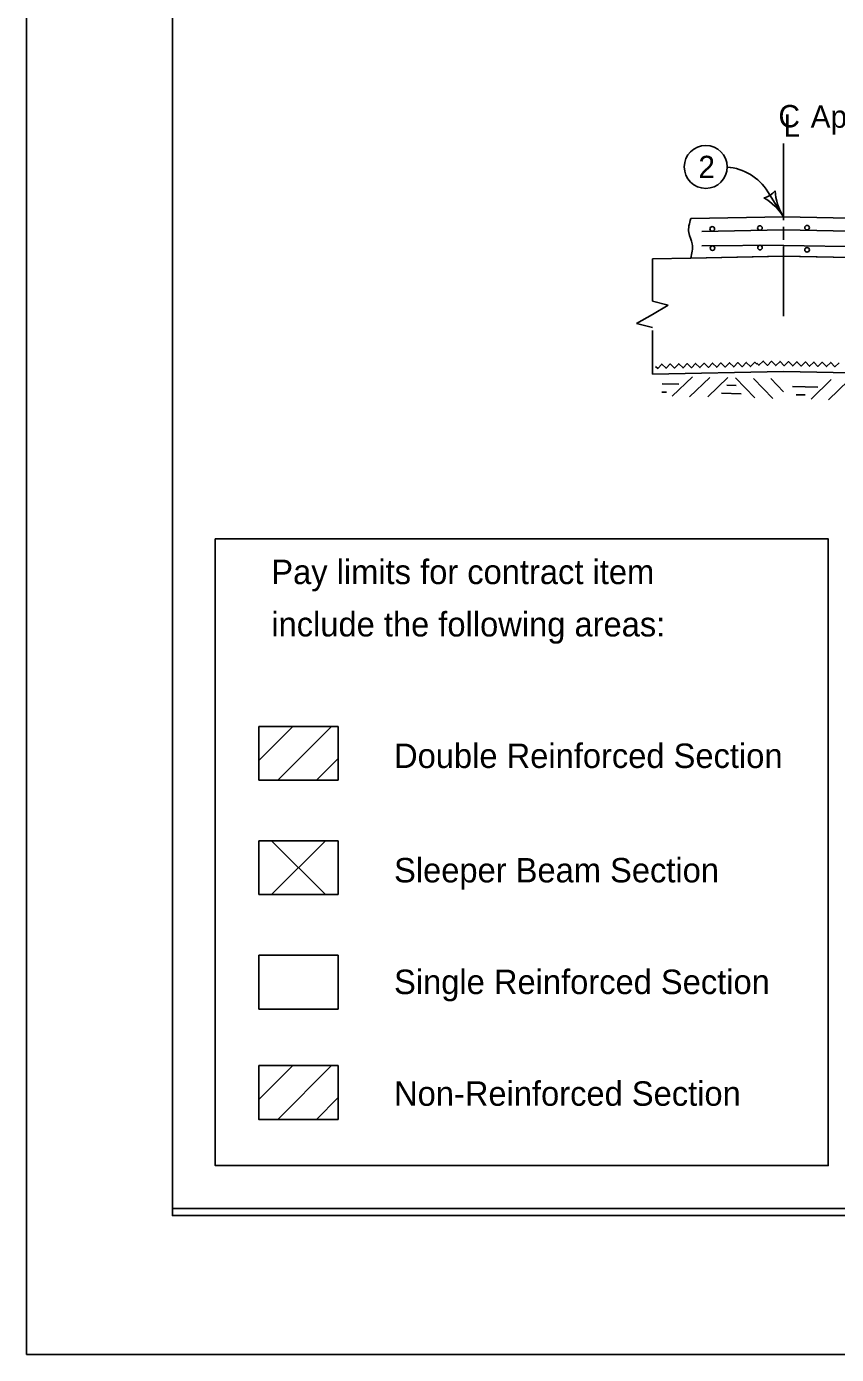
# Model space of a CAD drawing. Extents: x 10028 to 81668, y 6395 to 11634.
# Drawn here: x 13628 to 14208, y 7825 to 8776 of the extents above; entities that cross this region are included whole.
import ezdxf

# ---------------------------------------------------------------- set-up
doc = ezdxf.new("R2010")
doc.units = 0
for name, color, linetype in [('Default', 7, 'Continuous'), ('dsnCellElements', 7, 'Continuous'), ('dsnstdblockInterim', 7, 'Continuous'), ('dsnStdDimension', 7, 'Continuous'), ('ShtPlotIdentification', 7, 'Continuous')]:
    doc.layers.add(name, color=color, linetype=linetype)

msp = doc.modelspace()

# ---------------------------------------------------------------- linework, layer by layer
at = {"layer": 'Default'}
msp.add_lwpolyline([(13732.53, 9944.02), (16867.53, 9944.02), (16867.53, 7924.02), (13732.53, 7924.02)], close=True, dxfattribs=at)
at = {"layer": 'dsnCellElements'}
for p, q in [((14901.95, 8605.39), (14170.4, 8618.94)), ((13794.44, 8274.38), (13851.3, 8274.38)), ((13794.44, 8235.84), (13794.44, 8274.38)), ((13851.3, 8274.38), (13851.3, 8235.84)), ((13851.3, 8235.84), (13794.44, 8235.84)), ((13794.44, 8192.42), (13851.3, 8192.42)), ((13794.44, 8153.87), (13794.44, 8192.42)), ((13851.3, 8192.42), (13851.3, 8153.87)), ((13851.3, 8153.87), (13794.44, 8153.87)), ((13794.45, 8110.45), (13851.3, 8110.45)), ((13794.45, 8071.91), (13794.45, 8110.45)), ((13851.3, 8110.45), (13851.3, 8071.91)), ((13851.3, 8071.91), (13794.45, 8071.91))]:
    msp.add_line(p, q, dxfattribs=at)
at = {"layer": 'dsnstdblockInterim'}
msp.add_lwpolyline([(13732.53, 9939.02), (16867.53, 9939.02), (16867.53, 7929.02), (13732.53, 7929.02)], close=True, dxfattribs=at)
at = {"layer": 'dsnStdDimension'}
msp.add_lwpolyline([(13628.03, 7824.52), (16972.03, 7824.52), (16972.03, 10408.52), (13628.03, 10408.52)], close=True, dxfattribs=at)
at = {"layer": 'ShtPlotIdentification'}
for p, q in [((14159.21, 8657.4), (14170.44, 8639.49)), ((14170.44, 8639.49), (14104.06, 8638.15)), ((14170.44, 8639.49), (14104.06, 8638.15)), ((14880.69, 8625.23), (14170.44, 8639.49)), ((14170.44, 8639.49), (14880.69, 8625.23)), ((14170.4, 8630), (14111.89, 8628.83)), ((14170.4, 8630), (14902.07, 8615.32)), ((14170.4, 8619.17), (14111.88, 8618.54)), ((14104.06, 8609.79), (14076.5, 8609.24)), ((14076.5, 8609.24), (14076.5, 8578.98)), ((14171.01, 8611.13), (14104.06, 8609.79)), ((14104.06, 8609.79), (14169.87, 8611.11)), ((14169.87, 8611.13), (14170.44, 8611.12)), ((14169.87, 8611.13), (14918.97, 8596.1)), ((14170.44, 8611.12), (14171.01, 8611.13)), ((14171.01, 8611.11), (14918.97, 8596.1)), ((14076.5, 8578.98), (14087.84, 8576.14)), ((14087.84, 8576.14), (14076.5, 8569.53)), ((14076.5, 8569.53), (14065.15, 8562.91)), ((14065.15, 8562.91), (14076.5, 8560.07)), ((14076.5, 8558.07), (14076.5, 8526.81)), ((14170.44, 8528.7), (14076.5, 8526.81)), ((14105.13, 8524.75), (14090.7, 8510.9)), ((14117.57, 8524.28), (14103.15, 8510.42)), ((14130.58, 8524.24), (14116.16, 8510.39)), ((14135.99, 8524.13), (14149.84, 8509.71)), ((14148.99, 8523.65), (14162.85, 8509.22)), ((14161.44, 8523.62), (14170.54, 8514.15)), ((14170.44, 8528.7), (14987.03, 8512.31)), ((14204.66, 8522.76), (14190.23, 8508.9)), ((14217.1, 8522.28), (14202.68, 8508.42)), ((13794.44, 8274.38), (13851.3, 8274.38)), ((13794.44, 8274.38), (13794.44, 8235.84)), ((13794.44, 8249.96), (13818.86, 8274.38)), ((13808.01, 8235.84), (13846.55, 8274.38)), ((13851.3, 8274.38), (13851.3, 8235.84)), ((13835.7, 8235.84), (13851.3, 8251.44)), ((13851.3, 8235.84), (13794.44, 8235.84)), ((13794.44, 8192.42), (13851.3, 8192.42)), ((13794.44, 8192.42), (13794.44, 8153.87)), ((13842.15, 8192.42), (13803.6, 8153.87)), ((13803.6, 8192.42), (13842.15, 8153.87)), ((13851.3, 8192.42), (13851.3, 8153.87)), ((13851.3, 8153.87), (13794.44, 8153.87)), ((13794.45, 8110.45), (13851.3, 8110.45)), ((13794.45, 8110.45), (13794.45, 8071.91)), ((13851.3, 8110.45), (13851.3, 8071.91)), ((13851.3, 8071.91), (13794.45, 8071.91)), ((13794.45, 8007.02), (13818.86, 8031.44)), ((13808.01, 7992.89), (13846.55, 8031.44)), ((13835.7, 7992.89), (13851.3, 8008.5))]:
    msp.add_line(p, q, dxfattribs=at)
for points in [[(14170.44, 8691.85), (14170.44, 8637.02)], [(14170.44, 8632.29), (14170.44, 8622.84)], [(14170.44, 8618.11), (14170.44, 8568.26)], [(14169.87, 8611.11), (14169.87, 8611.13)], [(14171.01, 8611.13), (14171.01, 8611.11)], [(14078.76, 8532.29), (14080.31, 8530.81), (14083.27, 8533.9), (14086.36, 8530.93), (14089.32, 8534.02), (14092.4, 8531.06), (14095.37, 8534.14), (14098.45, 8531.18), (14101.42, 8534.26), (14104.5, 8531.3), (14107.47, 8534.38), (14110.55, 8531.42), (14113.51, 8534.51), (14116.6, 8531.54), (14119.56, 8534.63), (14122.64, 8531.66), (14125.61, 8534.75), (14128.7, 8531.78), (14131.66, 8534.87), (14134.75, 8531.91), (14137.71, 8534.99), (14140.79, 8532.03), (14143.75, 8535.11), (14146.84, 8532.15), (14149.81, 8535.23), (14151.35, 8533.75)], [(14151.35, 8534.61), (14152.83, 8533.07), (14155.92, 8536.03), (14158.88, 8532.94), (14161.97, 8535.91), (14164.93, 8532.82), (14168.01, 8535.79), (14170.97, 8532.7), (14174.06, 8535.67), (14177.03, 8532.58), (14180.11, 8535.54), (14183.08, 8532.46), (14186.16, 8535.42), (14189.12, 8532.34), (14192.21, 8535.3), (14195.17, 8532.22), (14198.25, 8535.18), (14201.22, 8532.1), (14204.31, 8535.06), (14207.27, 8531.97), (14210.36, 8534.93)], [(14083.29, 8513.91), (14086.55, 8513.85)], [(14083.41, 8519.71), (14095.44, 8519.47)], [(14129.91, 8518.76), (14136.44, 8518.63)], [(14176.91, 8517.84), (14194.97, 8517.47)], [(14125.96, 8512.98), (14140.15, 8512.69)], [(14179.56, 8511.98), (14186.09, 8511.85)]]:
    msp.add_lwpolyline(points, dxfattribs=at)
for points in [[(13763.26, 8408.69), (14202.55, 8408.69), (14202.55, 7959.76), (13763.26, 7959.76)], [(13794.45, 8031.44), (13851.3, 8031.44), (13851.3, 7992.89), (13794.45, 7992.89)]]:
    msp.add_lwpolyline(points, close=True, dxfattribs=at)
for centre, radius in [((14114.72, 8675.13), 15.36), ((14119.4, 8630.74), 1.65), ((14153.59, 8631.42), 1.65), ((14187.37, 8631.64), 1.65), ((14119.6, 8616.98), 1.65), ((14153.64, 8617.35), 1.65), ((14187.37, 8615.76), 1.65)]:
    msp.add_circle(centre, radius, dxfattribs=at)
for centre, radius, start, end in [((14127.18, 8637.31), 37.81, 32.09002, 85.59039), ((14152.55, 8668.03), 15.52, 284.35693, 319.82363), ((14152.55, 8668.03), 15.52, 284.35693, 319.82363), ((14204.48, 8660.83), 40.18, 184.01779, 212.09028), ((14204.48, 8660.83), 40.18, 184.01779, 212.09028), ((14136.4, 8618.14), 40.18, 32.09028, 60.16277), ((14136.4, 8618.14), 40.18, 32.09028, 60.16277)]:
    msp.add_arc(centre, radius, start, end, dxfattribs=at)
msp.add_spline([(14104.06, 8638.15), (14102.55, 8628.07), (14105.01, 8619.94), (14104.06, 8609.79)], degree=3, dxfattribs=at)
msp.add_spline([(14104.06, 8638.15), (14102.55, 8628.07), (14105.01, 8619.94), (14104.06, 8609.79)], degree=3, dxfattribs=at)

# ---------------------------------------------------------------- texts
at = {"layer": 'dsnCellElements'}
for s, height, p in [('C', 16, (14166.83, 8703.52)), ('L', 16, (14170.43, 8696.81)), ('Approach Roadway', 16, (14189.9, 8703.2)), ('2', 16, (14109.44, 8667.13)), ('Pay limits for contract item', 17.5, (13803.43, 8376.31)), ('include the following areas:', 17.5, (13803.43, 8338.81)), ('Double Reinforced Section', 17.5, (13891.38, 8244.61)), ('Sleeper Beam Section', 17.5, (13891.38, 8162.65)), ('Single Reinforced Section', 17.5, (13891.38, 8082.65)), ('Non-Reinforced Section', 17.5, (13891.38, 8002.65))]:
    msp.add_text(s, height=height, dxfattribs=at).set_placement(p)

doc.saveas('drawing.dxf')
